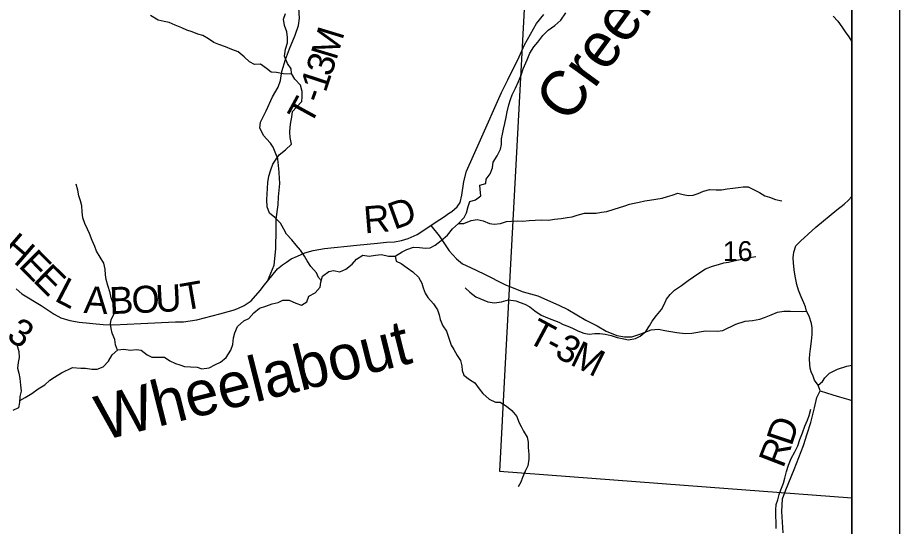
# Model space of a CAD drawing. Extents: x 0 to 34, y 0 to 22.
# Drawn here: x 7.144 to 9, y 15.589 to 16.66 of the extents above; entities that cross this region are included whole.
import ezdxf

# ---------------------------------------------------------------- set-up
doc = ezdxf.new("R2010")
doc.units = 0
for name, color, linetype in [('Default', 7, 'Continuous'), ('GM_X_County_Road', 7, 'Continuous'), ('GM_X_County_Road_Text', 7, 'Continuous'), ('GM_X_Minor_River', 7, 'Continuous'), ('GM_X_Minor_River_Text', 7, 'Continuous'), ('GM_X_Section_Text', 7, 'Continuous'), ('GM_X_Township_Road', 7, 'Continuous'), ('GM_X_Township_Road_Text', 7, 'Continuous'), ('SC_Scratch1', 7, 'Continuous'), ('SH_Data', 7, 'Continuous')]:
    doc.layers.add(name, color=color, linetype=linetype)

msp = doc.modelspace()

# ---------------------------------------------------------------- linework, layer by layer
at = {"layer": 'Default'}
msp.add_lwpolyline([(8.9, 15.6488), (8.9, 16.6804), (8.213, 16.7303), (8.1912, 16.3241), (8.1695, 15.9195), (8.158, 15.705), (8.5934, 15.672)], close=True, dxfattribs=at)
at = {"layer": 'GM_X_County_Road'}
for points in [[(7.1404, 16.0889), (7.1524, 16.0787), (7.1932, 16.054), (7.2205, 16.0358), (7.2346, 16.0283), (7.2533, 16.0223), (7.2731, 16.0189), (7.3238, 16.0137), (7.3457, 16.0134), (7.4032, 16.0158), (7.4758, 16.0194), (7.493, 16.0199), (7.5211, 16.0241), (7.5697, 16.0361), (7.5976, 16.0444), (7.607, 16.0478), (7.6205, 16.0538), (7.6351, 16.0639), (7.6541, 16.0852), (7.6637, 16.0975), (7.6697, 16.1055), (7.691, 16.1313), (7.7014, 16.1394), (7.7097, 16.1454), (7.7199, 16.1524), (7.7326, 16.1581), (7.7483, 16.1646), (7.7657, 16.1698), (7.7896, 16.174), (7.8575, 16.1807), (7.9015, 16.1854), (7.9203, 16.187), (7.9372, 16.1883), (7.952, 16.1909), (7.9661, 16.1951), (7.9848, 16.2036), (8.0135, 16.2222), (8.0271, 16.2312), (8.0382, 16.2386), (8.0454, 16.2436), (8.0505, 16.2475), (8.0579, 16.2518), (8.0635, 16.2565), (8.0691, 16.2618), (8.075, 16.2705), (8.0789, 16.2862), (8.0828, 16.3148), (8.0884, 16.3368), (8.1183, 16.4025), (8.1623, 16.5026), (8.1759, 16.5289), (8.1997, 16.5775), (8.2105, 16.603), (8.2297, 16.6363), (8.2361, 16.6479), (8.2514, 16.6664)], [(8.8334, 15.8741), (8.8289, 15.8864), (8.821, 15.8969), (8.8182, 15.9054), (8.8144, 15.9143), (8.8122, 15.9222), (8.8112, 15.9298), (8.8106, 15.9418), (8.8115, 15.9516), (8.8128, 15.963), (8.815, 15.9789), (8.8163, 15.9931), (8.8163, 16.007), (8.815, 16.0159), (8.8099, 16.0314), (8.8043, 16.0423), (8.8024, 16.051), (8.7991, 16.0596), (8.7934, 16.0724), (8.7876, 16.0861), (8.7841, 16.0985), (8.7806, 16.1154), (8.7788, 16.1291), (8.7771, 16.1438), (8.7765, 16.1542), (8.7779, 16.166), (8.7821, 16.1798), (8.7919, 16.1897), (8.8238, 16.2189), (8.8685, 16.2553), (8.8841, 16.2676), (8.8926, 16.2755), (8.899, 16.2826), (8.9, 16.2847)], [(8.7555, 15.5753), (8.7526, 15.6202), (8.7542, 15.6468), (8.7612, 15.6661), (8.7783, 15.7085), (8.7982, 15.7593), (8.806, 15.7836), (8.8137, 15.8079), (8.8213, 15.8386), (8.8264, 15.8601), (8.8334, 15.8741)], [(8.8334, 15.8741), (8.8596, 15.8658), (8.8739, 15.8617), (8.8938, 15.856), (8.9, 15.8542)]]:
    msp.add_lwpolyline(points, dxfattribs=at)
at = {"layer": 'GM_X_Minor_River'}
for points in [[(8.2036, 16.5387), (8.2082, 16.552), (8.2165, 16.5709), (8.2218, 16.5853), (8.2304, 16.5982), (8.2388, 16.6081), (8.2494, 16.6222), (8.2607, 16.6335), (8.2747, 16.6434), (8.2876, 16.6548), (8.2978, 16.67)], [(7.7212, 16.541), (7.7034, 16.5415), (7.689, 16.5445), (7.6773, 16.5453), (7.6678, 16.5532), (7.6549, 16.5623), (7.6421, 16.5612), (7.6318, 16.5672), (7.6208, 16.5775), (7.6079, 16.5881), (7.5947, 16.5926), (7.581, 16.5987), (7.5674, 16.6036), (7.5568, 16.6074), (7.5458, 16.6154), (7.5337, 16.6222), (7.5231, 16.6252), (7.511, 16.6298), (7.4996, 16.6336), (7.4894, 16.6385), (7.475, 16.6442), (7.4629, 16.6495), (7.4522, 16.6521), (7.4394, 16.6544), (7.4235, 16.6643)], [(7.7832, 16.1061), (7.7774, 16.1129), (7.7728, 16.1227), (7.7611, 16.136), (7.7531, 16.1481), (7.7478, 16.158), (7.7391, 16.1701), (7.7303, 16.1811), (7.7212, 16.1925), (7.7099, 16.2042), (7.7042, 16.2145), (7.6973, 16.2274), (7.6852, 16.2395), (7.6738, 16.2486), (7.6689, 16.2619), (7.6681, 16.2763), (7.6689, 16.2888), (7.6696, 16.3006), (7.6707, 16.3127), (7.6726, 16.3264), (7.6764, 16.3397), (7.6809, 16.3514), (7.6877, 16.3617), (7.6945, 16.3712), (7.7078, 16.3818), (7.7206, 16.3939), (7.7172, 16.4076), (7.7168, 16.419), (7.7176, 16.4296), (7.7191, 16.4402), (7.7209, 16.4504), (7.7224, 16.4622), (7.7308, 16.4717), (7.7421, 16.4835), (7.7429, 16.4929), (7.7425, 16.5043), (7.7394, 16.5176), (7.7273, 16.5301), (7.7205, 16.5422), (7.7193, 16.5521), (7.7117, 16.5635), (7.7056, 16.579), (7.7079, 16.5934), (7.7117, 16.6071), (7.712, 16.6181), (7.7101, 16.6302), (7.7056, 16.6435), (7.7033, 16.6568), (7.7074, 16.6689)], [(8.8608, 16.6627), (8.8703, 16.6528), (8.8787, 16.6407), (8.8859, 16.63), (8.8935, 16.6198), (8.8995, 16.6103), (8.9, 16.6096)], [(7.2595, 15.9237), (7.2766, 15.9218), (7.2865, 15.9218), (7.3001, 15.9196), (7.3111, 15.9196), (7.324, 15.9245), (7.3353, 15.937), (7.3429, 15.9499), (7.3546, 15.9605), (7.3671, 15.9617), (7.3807, 15.9598), (7.394, 15.9613), (7.4038, 15.9598), (7.4167, 15.95), (7.4262, 15.9454), (7.4398, 15.945), (7.4531, 15.945), (7.464, 15.9378), (7.4758, 15.9322), (7.4853, 15.9291), (7.4947, 15.9257), (7.5076, 15.925), (7.5216, 15.9238), (7.5315, 15.9204), (7.5466, 15.9227), (7.5606, 15.9295), (7.5705, 15.9349), (7.5826, 15.9447), (7.5924, 15.9599), (7.5965, 15.972), (7.5984, 15.9861), (7.6011, 15.9967), (7.6067, 16.01), (7.62, 16.0214), (7.6306, 16.0263), (7.6408, 16.0388), (7.6532, 16.0483), (7.6661, 16.0529), (7.6794, 16.0574), (7.6919, 16.0601), (7.7017, 16.065), (7.7153, 16.0654), (7.7293, 16.059), (7.7415, 16.0548), (7.7524, 16.0616), (7.757, 16.0734), (7.7698, 16.0806), (7.7808, 16.0928), (7.7823, 16.103), (7.7857, 16.1155), (7.7989, 16.1254), (7.8088, 16.1277), (7.822, 16.125), (7.8349, 16.1307), (7.8478, 16.1413), (7.8572, 16.1512), (7.8705, 16.1596), (7.8837, 16.1577), (7.897, 16.1596), (7.9098, 16.1611), (7.9246, 16.1581), (7.9386, 16.1577), (7.953, 16.1672), (7.9628, 16.1717), (7.9769, 16.1767), (7.9897, 16.1759), (8.0022, 16.1748), (8.0124, 16.1756), (8.0227, 16.1809), (8.0351, 16.1907), (8.0484, 16.2021), (8.0594, 16.215), (8.0718, 16.2264), (8.0836, 16.2389), (8.0885, 16.2488), (8.0919, 16.2621), (8.0956, 16.2727), (8.1078, 16.2761), (8.1191, 16.2849), (8.1172, 16.2978), (8.1168, 16.3072), (8.1297, 16.3107), (8.13, 16.3201), (8.1387, 16.3308), (8.1436, 16.344), (8.1448, 16.3558), (8.1535, 16.3687), (8.1603, 16.3831), (8.1621, 16.393), (8.1625, 16.4048), (8.1644, 16.4146), (8.1667, 16.4252), (8.1693, 16.4374), (8.1723, 16.4503), (8.1742, 16.4617), (8.1776, 16.4761), (8.181, 16.4878), (8.1847, 16.4973), (8.1919, 16.5117), (8.198, 16.5258), (8.2036, 16.5387)], [(7.3537, 15.9598), (7.35, 15.9715), (7.3481, 15.9825), (7.3428, 15.9958), (7.3405, 16.0053), (7.339, 16.0152), (7.3405, 16.0247), (7.3469, 16.0364), (7.348, 16.0493), (7.345, 16.0592), (7.3405, 16.0698), (7.3382, 16.0804), (7.3336, 16.096), (7.3302, 16.1089), (7.3287, 16.1187), (7.3283, 16.1301), (7.3252, 16.143), (7.3176, 16.1559), (7.3097, 16.1684), (7.3062, 16.1779), (7.3006, 16.1908), (7.2952, 16.2052), (7.2911, 16.2147), (7.2854, 16.2264), (7.2812, 16.2382), (7.2793, 16.2511), (7.2785, 16.264), (7.2762, 16.2742), (7.2728, 16.2845), (7.2701, 16.297), (7.2667, 16.3091)], [(8.0718, 16.2264), (8.0832, 16.2268), (8.0983, 16.2329), (8.1112, 16.2352), (8.1241, 16.2321), (8.137, 16.2268), (8.1472, 16.2253), (8.1601, 16.2268), (8.1726, 16.2306), (8.1832, 16.2314), (8.1964, 16.2322), (8.2074, 16.2318), (8.2203, 16.2326), (8.2335, 16.2337), (8.2475, 16.2341), (8.2612, 16.2337), (8.2737, 16.2356), (8.2877, 16.2371), (8.3009, 16.239), (8.3108, 16.2406), (8.3217, 16.2444), (8.3369, 16.2485), (8.3619, 16.2486), (8.3728, 16.2501), (8.3838, 16.252), (8.3997, 16.2569), (8.4111, 16.2603), (8.4221, 16.2641), (8.4319, 16.2676), (8.4417, 16.2691), (8.4523, 16.2714), (8.4641, 16.2744), (8.4743, 16.2755), (8.5008, 16.2801), (8.5122, 16.2831), (8.522, 16.2862), (8.5337, 16.2904), (8.5451, 16.2877), (8.5553, 16.2858), (8.5659, 16.2862), (8.5761, 16.29), (8.5879, 16.2949), (8.6011, 16.298), (8.6144, 16.2976), (8.6257, 16.2972), (8.6378, 16.2995), (8.6496, 16.301), (8.6609, 16.3022), (8.6712, 16.3041), (8.6814, 16.3041), (8.7056, 16.292), (8.7166, 16.2848), (8.7269, 16.2821), (8.739, 16.2772), (8.7526, 16.2742)], [(7.9386, 16.1577), (7.9409, 16.1475), (7.9511, 16.1422), (7.964, 16.1334), (7.9758, 16.1247), (7.9879, 16.1137), (7.9944, 16.1008), (7.9978, 16.0913), (8.002, 16.08), (8.0073, 16.0705), (8.019, 16.0576), (8.0277, 16.0447), (8.0308, 16.0341), (8.0331, 16.0246), (8.0391, 16.0109), (8.0463, 15.9999), (8.0505, 15.987), (8.0566, 15.9707), (8.0619, 15.9613), (8.0687, 15.9484), (8.076, 15.9381), (8.079, 15.9267), (8.0798, 15.9173), (8.0832, 15.9074), (8.0949, 15.8983), (8.1063, 15.8915), (8.1154, 15.8786), (8.123, 15.8687), (8.1366, 15.857), (8.1495, 15.8505), (8.1594, 15.8505), (8.1726, 15.8422), (8.1844, 15.8327), (8.1946, 15.8202), (8.1988, 15.8084), (8.2037, 15.799), (8.209, 15.7891), (8.2162, 15.7766), (8.2185, 15.766), (8.2182, 15.755), (8.2201, 15.7409), (8.2197, 15.7307), (8.2175, 15.7163), (8.2122, 15.7053), (8.2069, 15.6916), (8.2031, 15.6821), (8.1978, 15.6719)], [(8.086, 16.0914), (8.0959, 16.0823), (8.1084, 16.0724), (8.1334, 16.0618), (8.1478, 16.0595), (8.1625, 16.0618), (8.1773, 16.0656), (8.1924, 16.0637), (8.2019, 16.06), (8.2118, 16.0569), (8.222, 16.0512), (8.2326, 16.0429), (8.2459, 16.0338), (8.2595, 16.0277), (8.283, 16.0186), (8.2925, 16.0137), (8.3023, 16.0103), (8.3118, 16.0061), (8.3231, 16.0008), (8.336, 15.9955), (8.347, 15.9936), (8.3587, 15.9948), (8.3697, 15.9948), (8.3803, 15.9933), (8.3936, 15.991), (8.4061, 15.9868), (8.4201, 15.9838), (8.43, 15.9815), (8.4443, 15.9842), (8.4546, 15.9895), (8.4663, 15.9994), (8.4738, 16.0115), (8.4799, 16.021), (8.4886, 16.0332), (8.4992, 16.0457), (8.5045, 16.0559), (8.5094, 16.0673), (8.5177, 16.0768), (8.5264, 16.0863), (8.5411, 16.0961), (8.5555, 16.1064), (8.5665, 16.1144), (8.5801, 16.1235), (8.5922, 16.1314), (8.6066, 16.1368), (8.6191, 16.1406), (8.6305, 16.1436), (8.6403, 16.1455), (8.6513, 16.1478), (8.6611, 16.1501), (8.6725, 16.1524), (8.6846, 16.155), (8.6975, 16.1573)], [(7.1422, 15.972), (7.1464, 15.9572), (7.1472, 15.9443), (7.1446, 15.9337), (7.1431, 15.9219), (7.1461, 15.9113), (7.1485, 15.9003), (7.15, 15.8863), (7.1512, 15.8734), (7.1486, 15.8624), (7.1479, 15.8495), (7.1456, 15.8385), (7.1339, 15.8328)], [(7.1481, 15.8542), (7.1596, 15.8606), (7.1735, 15.8685), (7.1868, 15.8788), (7.2007, 15.8868), (7.2113, 15.8967), (7.2211, 15.9032), (7.2359, 15.9119), (7.2595, 15.9237)], [(8.7409, 15.5845), (8.7405, 15.5978), (8.7401, 15.6103), (8.7401, 15.624), (8.7408, 15.635), (8.7439, 15.6452), (8.7469, 15.6558), (8.7503, 15.6661), (8.7563, 15.6797), (8.7586, 15.6907), (8.7624, 15.7044), (8.7665, 15.718), (8.7725, 15.7317), (8.7801, 15.7457), (8.7861, 15.7587), (8.7907, 15.7719), (8.796, 15.786), (8.8009, 15.7996), (8.8065, 15.8129), (8.8099, 15.8224), (8.8137, 15.836)]]:
    msp.add_lwpolyline(points, dxfattribs=at)
at = {"layer": 'GM_X_Township_Road'}
for points in [[(7.6944, 16.3334), (7.6944, 16.3343), (7.6913, 16.3626), (7.6858, 16.3764), (7.6816, 16.3876), (7.6762, 16.3957), (7.6673, 16.4048), (7.6619, 16.4113), (7.6535, 16.4274), (7.6551, 16.4397), (7.667, 16.4641), (7.6803, 16.4932), (7.6923, 16.5133), (7.697, 16.5274), (7.6999, 16.5463), (7.7079, 16.5717), (7.7159, 16.5946), (7.7282, 16.6229), (7.735, 16.6434), (7.7373, 16.6585), (7.735, 16.6918)], [(7.6697, 16.1055), (7.684, 16.1391), (7.6874, 16.1732), (7.6879, 16.2146), (7.6879, 16.2359), (7.6921, 16.2658), (7.6931, 16.283), (7.6954, 16.3111), (7.6944, 16.3334)], [(8.0135, 16.2222), (8.0314, 16.2006), (8.052, 16.1693), (8.0674, 16.1522), (8.0806, 16.1417), (8.0968, 16.1339), (8.1254, 16.1205), (8.1705, 16.0973), (8.2079, 16.0824), (8.239, 16.074), (8.2594, 16.0654), (8.2833, 16.0549), (8.3022, 16.0456), (8.3399, 16.023), (8.3637, 16.0112), (8.3829, 15.9999), (8.4055, 15.9909), (8.4215, 15.988), (8.437, 15.9882), (8.4555, 15.9944), (8.4773, 16.0024), (8.4931, 16.0044), (8.5059, 16.0016), (8.5312, 15.9971), (8.5491, 15.995), (8.5633, 15.996), (8.5919, 16.0003), (8.6174, 15.9999), (8.6281, 16.0012), (8.6559, 16.0145), (8.6751, 16.0207), (8.6905, 16.0222), (8.7059, 16.0252), (8.7162, 16.0287), (8.7304, 16.0345), (8.7432, 16.0396), (8.7567, 16.0419), (8.7707, 16.0419), (8.7969, 16.0411), (8.8043, 16.0423)], [(8.8289, 15.8864), (8.8383, 15.8938), (8.8432, 15.9016), (8.853, 15.9114), (8.8698, 15.9197), (8.8891, 15.9266), (8.9, 15.9284)]]:
    msp.add_lwpolyline(points, dxfattribs=at)
at = {"layer": 'SC_Scratch1'}
msp.add_lwpolyline([(5.0535, 14.1), (8.9, 14.1), (8.9, 18.7389), (8.2061, 18.7863), (7.2159, 18.8539), (6.8273, 18.8804), (5.9889, 18.9377), (5.4885, 18.9719), (5.4007, 18.9779), (5.3662, 18.4999), (5.3506, 18.2846), (5.2869, 17.4026), (5.2761, 17.2534), (5.1794, 15.9156), (5.1049, 14.8414), (5.0814, 14.5016)], close=True, dxfattribs=at)
at = {"layer": 'SH_Data'}
for p, q in [((9, 21), (9, 14)), ((8.9, 20.9), (8.9, 14.1))]:
    msp.add_line(p, q, dxfattribs=at)

# ---------------------------------------------------------------- texts
at = {"layer": 'GM_X_County_Road_Text'}
for s, rotation, p in [('R', 4.7474, (7.8744, 16.2056)), ('D', 19.8619, (7.9366, 16.2129)), ('H', 319.1869, (7.1065, 16.1683)), ('E', 314.7515, (7.1435, 16.1364)), ('E', 315.4597, (7.1739, 16.1057)), ('L', 332.472, (7.2191, 16.0651)), ('O', 2.6005, (7.3848, 16.0374)), ('U', 2.93, (7.4351, 16.0397)), ('T', 9.8547, (7.4925, 16.0431)), ('A', 356.7987, (7.282, 16.0385)), ('B', 2.163, (7.3377, 16.0357)), ('3', 327.2842, (7.1179, 15.9842)), ('D', 71.5078, (8.7729, 15.756)), ('R', 68.9204, (8.7552, 15.7098))]:
    msp.add_text(s, height=0.0568, rotation=rotation, dxfattribs=at).set_placement(p)
at = {"layer": 'GM_X_Minor_River_Text'}
for s, height, rotation, p in [('Creek', 0.0947, 53.9563, (8.3038, 16.4346)), ('Wheelabout', 0.09469, 14.1084, (7.3226, 15.7691))]:
    msp.add_text(s, height=height, rotation=rotation, dxfattribs=at).set_placement(p)
at = {"layer": 'GM_X_Section_Text'}
msp.add_text('16', height=0.04186, rotation=0, dxfattribs=at).set_placement((8.6285, 16.1475))
at = {"layer": 'GM_X_Township_Road_Text'}
for s, rotation, p in [('M', 73.1232, (7.8144, 16.5684)), ('3', 71.9011, (7.8032, 16.5338)), ('1', 71.6906, (7.7921, 16.5004)), ('-', 70.7865, (7.7841, 16.4774)), ('T', 61.3704, (7.7596, 16.4308)), ('T', 331.7442, (8.2135, 15.9789)), ('3', 331.9286, (8.2717, 15.9477)), ('-', 331.7906, (8.251, 15.9588)), ('M', 333.6327, (8.3042, 15.9304))]:
    msp.add_text(s, height=0.0568, rotation=rotation, dxfattribs=at).set_placement(p)

doc.saveas('drawing.dxf')
